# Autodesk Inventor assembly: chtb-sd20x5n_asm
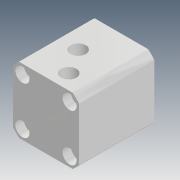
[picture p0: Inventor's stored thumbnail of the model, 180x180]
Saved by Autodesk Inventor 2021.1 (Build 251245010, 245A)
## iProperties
Company: Microsoft
Created: 2018-04
Part Number: chtb-sd20x5n_asm
Description: STEP AP214
Document SubType Name: Assembly
Designer: user
Title: chtb-sd20x5n_asm.STEP
Author: Windows
Revision Number: ÈÎºÎ
Sending System: SolidWorks 2015
Preprocessor: SwSTEP 2.0
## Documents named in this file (4)
- D:\Vault_2016\Projekty\Clamptek\Hydraulic\CHTB\CHTB-20\Inventor\CHTB-SD20x5N\chtb-sd20x5n_asm.iam
- D:\Vault_2016\Projekty\Clamptek\Hydraulic\CHTB\CHTB-20\Inventor\CHTB-SD20x5N\CHTB-SD20X5NBT.ipt
- D:\Vault_2016\Projekty\Clamptek\Hydraulic\CHTB\CHTB-20\Inventor\CHTB-SD20x5N\CHTB-SD20X5NHSG.ipt
- D:\Vault_2016\Projekty\Clamptek\Hydraulic\CHTB\CHTB-20\Inventor\CHTB-SD20x5N\QG.ipt
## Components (3 placed, 3 different names)
1. CHTB-SD20X5NBT_1
2. CHTB-SD20X5NHSG_2
3. QG_3
